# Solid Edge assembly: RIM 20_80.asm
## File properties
Title: Zylinder
Author: ahadarics
Template: iso metric assembly.asm
Last saved by: ahadarics
Revision: 8
Application: Solid Edge
Username: ahadarics
Dokumentum tartalom típus: 1
Document Number: RIM 20/80
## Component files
Kit_2.par
Profilrohr.par
Kolbenstange.par
Kit_1.par
Mutter_1.par
Mutter_2.par
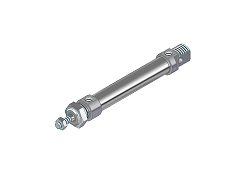
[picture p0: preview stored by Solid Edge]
